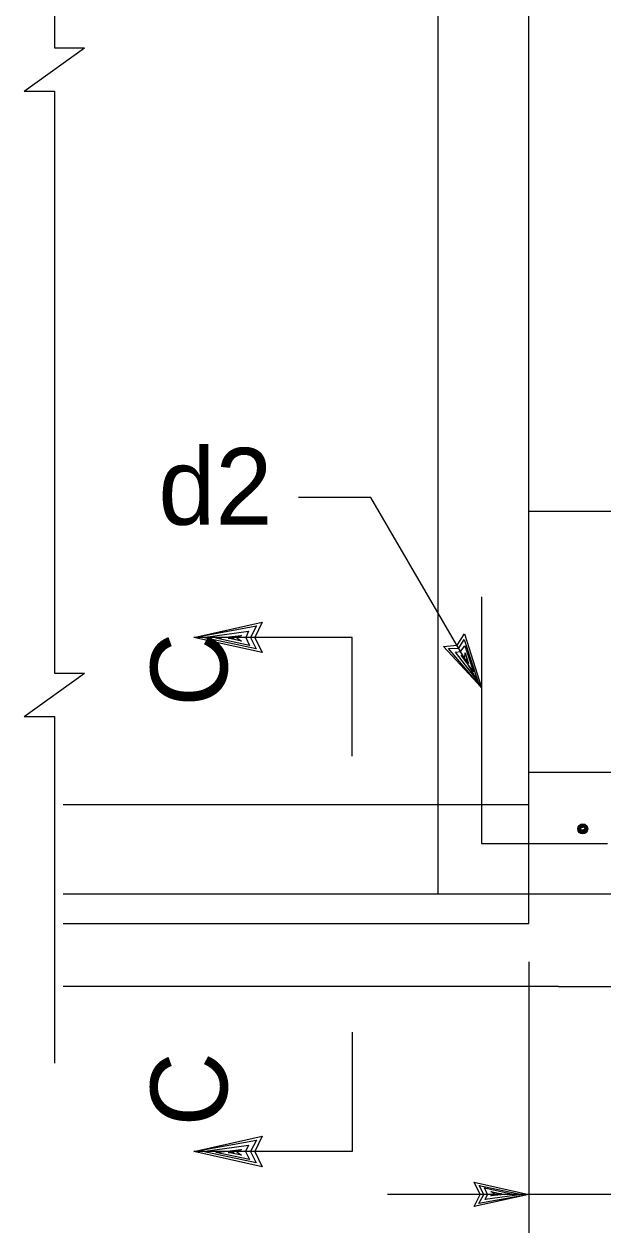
# Model space of a CAD drawing. Extents: x -0.08 to 2.83, y -0.03 to 1.92.
# Drawn here: x 0.6374 to 0.7357, y 1.4595 to 1.6645 of the extents above; entities that cross this region are included whole.
import ezdxf

# ---------------------------------------------------------------- set-up
doc = ezdxf.new("R2010")
doc.units = 0
for name, color, linetype in [('1', 7, 'Continuous'), ('50', 7, 'Continuous'), ('51', 7, 'Continuous'), ('55', 7, 'Continuous'), ('57', 7, 'Continuous')]:
    doc.layers.add(name, color=color, linetype=linetype)

msp = doc.modelspace()

# ---------------------------------------------------------------- linework, layer by layer
at = {"layer": '1'}
msp.add_line((0.72312, 1.51702), (0.72312, 1.53214), dxfattribs=at)
at = {"layer": '50'}
for p, q in [((0.7077, 1.51702), (0.7077, 1.70926)), ((0.72312, 1.51199), (0.72312, 1.70926)), ((0.72312, 1.58193), (1.05185, 1.58196)), ((0.72312, 1.53763), (1.05185, 1.53765)), ((0.64405, 1.53214), (0.72312, 1.53214)), ((0.64404, 1.51702), (0.72312, 1.51702)), ((0.72312, 1.51702), (1.05184, 1.51705)), ((0.64404, 1.51199), (0.72312, 1.51199)), ((0.72816, 1.50129), (0.64404, 1.50129)), ((0.72816, 1.50129), (1.05185, 1.50131))]:
    msp.add_line(p, q, dxfattribs=at)
at = {"layer": '51'}
for p, q in [((0.71509, 1.56737), (0.71509, 1.52554)), ((0.71509, 1.52554), (0.73644, 1.52554))]:
    msp.add_line(p, q, dxfattribs=at)
for points in [[(0.73235, 1.52881), (0.73267, 1.5287), (0.73291, 1.52848), (0.73304, 1.52819), (0.73305, 1.5279), (0.73298, 1.52768), (0.73283, 1.5275), (0.73263, 1.52735), (0.73243, 1.52727), (0.73216, 1.52725), (0.7319, 1.52732), (0.73172, 1.52744), (0.73157, 1.52766), (0.73149, 1.5279), (0.73149, 1.5282), (0.73161, 1.52845), (0.73176, 1.52863), (0.73192, 1.52873), (0.73212, 1.52879), (0.7323, 1.52878), (0.73249, 1.52871), (0.73268, 1.52862), (0.73285, 1.52848), (0.73293, 1.52833), (0.733, 1.5282), (0.733, 1.52806), (0.733, 1.52787), (0.73293, 1.52772), (0.73283, 1.52759), (0.73273, 1.52748), (0.73259, 1.52738), (0.7324, 1.52733), (0.73221, 1.52732), (0.73206, 1.52734), (0.73186, 1.5274), (0.73176, 1.52747), (0.73167, 1.5276), (0.73159, 1.52772), (0.73155, 1.52787), (0.73153, 1.52805), (0.73158, 1.52827), (0.73167, 1.52845), (0.7318, 1.52858), (0.73202, 1.5287), (0.73221, 1.52874), (0.7324, 1.52869), (0.73259, 1.52861), (0.73276, 1.52848), (0.73287, 1.52836), (0.73293, 1.52822), (0.73295, 1.52803), (0.73291, 1.52785), (0.73284, 1.52772), (0.73271, 1.52758), (0.73254, 1.52745), (0.73236, 1.5274), (0.73216, 1.52739), (0.73199, 1.52741), (0.7318, 1.52751), (0.73169, 1.52766), (0.73163, 1.52781), (0.7316, 1.52803), (0.73164, 1.52825), (0.73172, 1.52842), (0.73184, 1.52853), (0.73198, 1.52862), (0.73212, 1.52866), (0.73229, 1.52866), (0.73243, 1.52861), (0.73257, 1.52854), (0.73267, 1.52846), (0.73281, 1.52833), (0.73288, 1.52819), (0.73289, 1.52803), (0.73286, 1.52788), (0.73272, 1.52769), (0.73257, 1.52758), (0.73237, 1.52748), (0.73217, 1.52747), (0.73202, 1.52751), (0.73192, 1.52753), (0.73176, 1.52765), (0.73172, 1.52777), (0.73165, 1.52796), (0.73168, 1.52817), (0.73177, 1.52836), (0.73188, 1.52849), (0.73203, 1.52858), (0.73219, 1.52861), (0.73236, 1.52857), (0.73255, 1.52848), (0.7327, 1.52837), (0.73281, 1.52827), (0.73286, 1.5281), (0.73283, 1.52803), (0.73281, 1.52791), (0.73274, 1.52782), (0.73261, 1.52768), (0.73252, 1.52763), (0.73242, 1.52758), (0.73233, 1.52754)], [(0.73233, 1.52754), (0.73208, 1.52759), (0.73192, 1.5276), (0.73184, 1.52769), (0.73176, 1.52781), (0.73172, 1.52796), (0.73172, 1.52812), (0.73179, 1.52827), (0.73188, 1.5284), (0.73198, 1.52848), (0.73211, 1.52854), (0.73231, 1.52852), (0.73248, 1.52845), (0.73261, 1.52836), (0.73274, 1.52826), (0.7328, 1.52812), (0.73273, 1.52796), (0.73268, 1.52789), (0.73259, 1.52779), (0.7325, 1.52772), (0.7324, 1.52766), (0.73231, 1.52764), (0.73221, 1.52763), (0.73212, 1.52765), (0.73198, 1.52768), (0.7319, 1.52772), (0.73187, 1.52776), (0.73181, 1.52785), (0.73179, 1.52791), (0.73178, 1.52798), (0.73178, 1.52808), (0.73179, 1.52813), (0.73181, 1.52822), (0.73187, 1.52829), (0.73206, 1.52844), (0.73216, 1.52848), (0.73228, 1.52847), (0.7324, 1.52843), (0.73247, 1.52839), (0.73257, 1.52832), (0.73263, 1.52827), (0.7327, 1.52819), (0.73273, 1.52811), (0.73268, 1.52798), (0.73266, 1.52793), (0.73259, 1.52787), (0.73252, 1.52781), (0.73246, 1.52777), (0.73239, 1.52774), (0.73233, 1.5277), (0.73226, 1.52768), (0.73223, 1.52768), (0.73214, 1.5277), (0.7321, 1.52772), (0.73203, 1.52774), (0.73197, 1.52778), (0.7319, 1.52783), (0.73187, 1.52788), (0.73185, 1.52798), (0.73185, 1.52805), (0.73185, 1.52812), (0.73188, 1.52819), (0.73194, 1.52827), (0.73201, 1.52832), (0.73207, 1.52836), (0.73214, 1.52839), (0.73221, 1.52841), (0.73228, 1.52836), (0.73235, 1.52834), (0.73245, 1.5283), (0.73252, 1.52826), (0.73257, 1.52821), (0.73261, 1.52814), (0.7326, 1.52805), (0.73257, 1.52796), (0.73254, 1.52792), (0.73246, 1.52786), (0.7324, 1.52783), (0.73236, 1.52781), (0.73231, 1.52779), (0.73225, 1.52777), (0.73219, 1.52777), (0.73214, 1.52777), (0.7321, 1.52778), (0.73206, 1.52782), (0.73202, 1.52785), (0.73199, 1.52787), (0.73197, 1.52789), (0.73194, 1.52791), (0.73192, 1.52796), (0.73192, 1.52801), (0.73194, 1.52808), (0.73195, 1.52813), (0.73197, 1.52819), (0.732, 1.52823), (0.73203, 1.52827), (0.73207, 1.5283), (0.73214, 1.52831), (0.73219, 1.52832), (0.73224, 1.52833), (0.73229, 1.52831)]]:
    msp.add_lwpolyline(points, dxfattribs=at)
msp.add_circle((0.73227, 1.52802), 0.00084, dxfattribs=at)
at = {"layer": '55'}
for p, q in [((0.64258, 1.72124), (0.64257, 1.6605)), ((0.63744, 1.65314), (0.6477, 1.6605)), ((0.64257, 1.6605), (0.6477, 1.6605)), ((0.63744, 1.65314), (0.64258, 1.65314)), ((0.64258, 1.65314), (0.64257, 1.55443)), ((0.6963, 1.58425), (0.68403, 1.58425)), ((0.71509, 1.55201), (0.6963, 1.58425)), ((0.71092, 1.55915), (0.71222, 1.56107)), ((0.71222, 1.56107), (0.71509, 1.55201)), ((0.70861, 1.55897), (0.71092, 1.55915)), ((0.71509, 1.55201), (0.70861, 1.55897)), ((0.70945, 1.55861), (0.71123, 1.55864)), ((0.71509, 1.55201), (0.70945, 1.55861)), ((0.71067, 1.558), (0.71153, 1.55811)), ((0.71123, 1.55864), (0.71215, 1.56011)), ((0.71153, 1.55811), (0.71223, 1.55906)), ((0.71215, 1.56011), (0.71448, 1.55306)), ((0.71223, 1.55906), (0.71371, 1.55464)), ((0.71448, 1.55306), (0.71067, 1.558)), ((0.71371, 1.55464), (0.71161, 1.55745)), ((0.71161, 1.55745), (0.71223, 1.55704)), ((0.71223, 1.55704), (0.71229, 1.55785)), ((0.71229, 1.55785), (0.71287, 1.55609)), ((0.71287, 1.55609), (0.71243, 1.55684)), ((0.63744, 1.54706), (0.6477, 1.55443)), ((0.64257, 1.55443), (0.6477, 1.55443)), ((0.63744, 1.54706), (0.64258, 1.54706)), ((0.64258, 1.54706), (0.64258, 1.48827)), ((0.72312, 1.50548), (0.72312, 1.45949)), ((0.71487, 1.466), (0.71384, 1.46807)), ((0.71384, 1.46807), (0.72312, 1.466)), ((0.72312, 1.466), (0.6991, 1.466)), ((0.72312, 1.466), (0.71384, 1.46394)), ((0.71384, 1.46394), (0.71487, 1.466)), ((0.72312, 1.466), (0.71461, 1.46446)), ((0.71461, 1.46446), (0.71545, 1.466)), ((0.71545, 1.466), (0.71467, 1.46755)), ((0.71467, 1.46755), (0.7219, 1.466)), ((0.71609, 1.466), (0.71558, 1.4671)), ((0.71558, 1.4671), (0.72016, 1.46613)), ((0.7219, 1.466), (0.71571, 1.46516)), ((0.71571, 1.46516), (0.71609, 1.466)), ((0.71732, 1.46608), (0.71667, 1.46652)), ((0.71667, 1.46652), (0.71848, 1.46613)), ((0.72016, 1.46613), (0.71667, 1.46575)), ((0.71667, 1.46575), (0.71732, 1.46608)), ((0.71848, 1.46613), (0.71765, 1.46613)), ((0.74128, 1.466), (0.72312, 1.466))]:
    msp.add_line(p, q, dxfattribs=at)
at = {"layer": '57'}
for p, q in [((0.66626, 1.5605), (0.67787, 1.56308)), ((0.66626, 1.5605), (0.67691, 1.56244)), ((0.67691, 1.56244), (0.67586, 1.5605)), ((0.67787, 1.56308), (0.67659, 1.5605)), ((0.69314, 1.5605), (0.66626, 1.5605)), ((0.67787, 1.55793), (0.66626, 1.5605)), ((0.66779, 1.5605), (0.67553, 1.56155)), ((0.67682, 1.55857), (0.66779, 1.5605)), ((0.66997, 1.56034), (0.67432, 1.56083)), ((0.6757, 1.55913), (0.66997, 1.56034)), ((0.67432, 1.55986), (0.67207, 1.56034)), ((0.67207, 1.56034), (0.67311, 1.56034)), ((0.67432, 1.56083), (0.67352, 1.56042)), ((0.67352, 1.56042), (0.67432, 1.55986)), ((0.67553, 1.56155), (0.67505, 1.5605)), ((0.67505, 1.5605), (0.6757, 1.55913)), ((0.67586, 1.5605), (0.67682, 1.55857)), ((0.67659, 1.5605), (0.67787, 1.55793)), ((0.69313, 1.54034), (0.69314, 1.5605)), ((0.69313, 1.49352), (0.69313, 1.4733)), ((0.66625, 1.47329), (0.67787, 1.47587)), ((0.66625, 1.47329), (0.6769, 1.47523)), ((0.66778, 1.47329), (0.67553, 1.47435)), ((0.67553, 1.47435), (0.67504, 1.47329)), ((0.6769, 1.47523), (0.67585, 1.47329)), ((0.67787, 1.47587), (0.67658, 1.47329)), ((0.69313, 1.4733), (0.66625, 1.47329)), ((0.67787, 1.47071), (0.66625, 1.47329)), ((0.67682, 1.47136), (0.66778, 1.47329)), ((0.66997, 1.47313), (0.67432, 1.47362)), ((0.67569, 1.47192), (0.66997, 1.47313)), ((0.67432, 1.47265), (0.67207, 1.47313)), ((0.67207, 1.47313), (0.67311, 1.47313)), ((0.67432, 1.47362), (0.67352, 1.47321)), ((0.67352, 1.47321), (0.67432, 1.47265)), ((0.67504, 1.47329), (0.67569, 1.47192)), ((0.67585, 1.47329), (0.67682, 1.47136)), ((0.67658, 1.47329), (0.67787, 1.47071))]:
    msp.add_line(p, q, dxfattribs=at)

# ---------------------------------------------------------------- texts
for s, height, rotation, p in [('d2', 0.013021, 0.0033, (0.66022, 1.5796)), ('C', 0.01302, 90, (0.67193, 1.54874)), ('C', 0.01302, 90, (0.67193, 1.47754))]:
    msp.add_text(s, height=height, rotation=rotation, dxfattribs=at).set_placement(p)

doc.saveas('drawing.dxf')
